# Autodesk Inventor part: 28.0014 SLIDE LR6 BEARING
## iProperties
Created: 2007-06
Part Number: 28.0014 SLIDE LR6 BEARING
Material: Steel
Document SubType Name: Modeling
Designer: Andy Moles
Mass: 32.8062 g
Surface Area: 18.8769 cm^2
Volume: 4.17914 cm^3
Density: 7.85 g/cm^3
Author: Andy Moles
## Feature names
1. Base1
